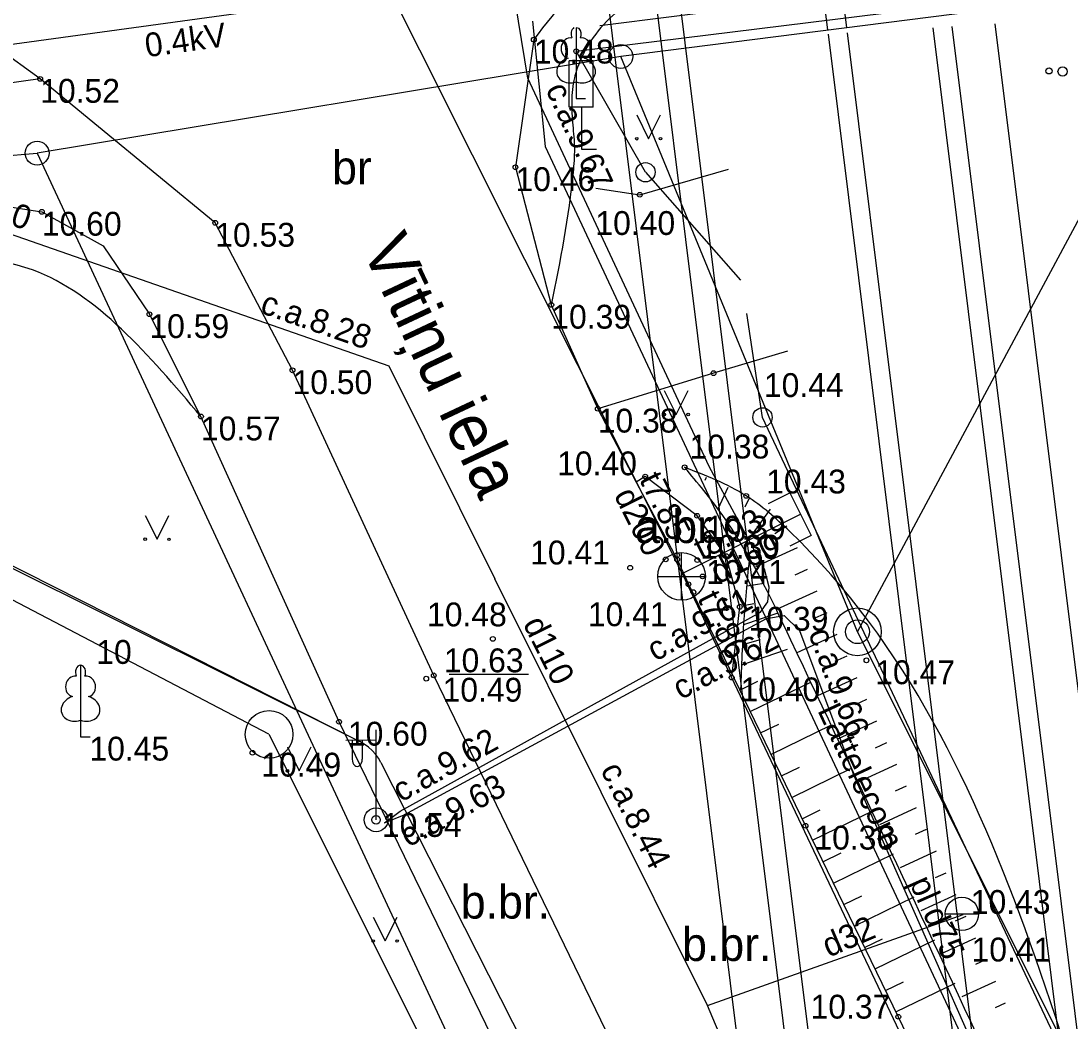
# Model space of a CAD drawing. Extents: x 502312.8 to 502402.4, y 308528.5 to 308602.
# Drawn here: x 502364.65 to 502386.67, y 308567.38 to 308588.36 of the extents above; entities that cross this region are included whole.
import ezdxf

# ---------------------------------------------------------------- set-up
doc = ezdxf.new("R2010")
doc.units = 0
for name, color, linetype in [('10', 7, 'Continuous'), ('24', 7, 'Continuous'), ('APGR_ELEM_####_####_#', 7, 'Continuous'), ('APGR_SARK_####_####_#', 7, 'Continuous'), ('APGS_ACRL_####_####_#', 7, 'Continuous'), ('APGS_ACRL_####_TKST_#', 7, 'Continuous'), ('APGS_ELEM_####_####_#', 7, 'Continuous'), ('APGS_VADP_ZSPR_####_I', 7, 'Continuous'), ('CELI_CAPM_####_####_#', 7, 'Continuous'), ('CELI_CMAL_####_####_#', 7, 'Continuous'), ('CELI_CSEG_####_TKST_#', 7, 'Continuous'), ('CELI_ELEM_####_####_#', 7, 'Continuous'), ('CELI_IELA_####_TKST_#', 7, 'Continuous'), ('ELEK_ACRL_####_####_#', 7, 'Continuous'), ('ELEK_VADP_ZSPR_####_#', 7, 'Continuous'), ('ELEK_VADV_ASP1_####_#', 7, 'Continuous'), ('ELEK_VADV_ZSPR_####_#', 7, 'Continuous'), ('ELEK_VADV_ZSPR_TKST_#', 7, 'Continuous'), ('Level 51-1', 7, 'Continuous'), ('NORB_ELEM_####_####_#', 7, 'Continuous'), ('NORB_ZOGS_BARJ_####_#', 7, 'Continuous'), ('NORB_ZOGS_ZSTP_####_#', 7, 'Continuous'), ('RELJ_AATZ_####_TKST_#', 7, 'Continuous'), ('RELJ_ELEM_####_####_#', 7, 'Continuous'), ('RELJ_NOGA_####_####_#', 7, 'Continuous'), ('RELJ_NOGL_####_####_#', 7, 'Continuous'), ('SAKK_KKAN_####_####_#', 7, 'Continuous'), ('SAKK_KKAN_####_TKST_#', 7, 'Continuous'), ('SKAN_ELEM_####_####_#', 7, 'Continuous'), ('SKAN_ELEM_PAST_TKST_#', 7, 'Continuous'), ('SKAN_VADP_PAST_####_I', 7, 'Continuous'), ('SKAN_VADP_PAST_TKST_I', 7, 'Continuous'), ('TERT_DIAM_####_TKST_#', 7, 'Continuous'), ('TERT_DZOG_####_####_#', 7, 'Continuous'), ('TERT_ELEM_####_####_#', 7, 'Continuous'), ('TERT_KONT_####_####_#', 7, 'Continuous'), ('UDTK_ELEM_####_####_#', 7, 'Continuous'), ('UDTK_ELEM_####_TKST_#', 7, 'Continuous'), ('UDTK_VADP_UDEN_####_#', 7, 'Continuous'), ('UDTK_VADP_UDEN_TKST_#', 7, 'Continuous')]:
    doc.layers.add(name, color=color, linetype=linetype)

msp = doc.modelspace()

# ---------------------------------------------------------------- linework, layer by layer
at = {"layer": '10'}
for centre in [(502377.227, 308587.621), (502364.984, 308585.593), (502382.191, 308575.562)]:
    msp.add_circle(centre, 0.25, dxfattribs=at)
at = {"layer": '24'}
for p, q in [((502402.407, 308590.821), (502377.227, 308587.621)), ((502377.227, 308587.621), (502364.984, 308585.593)), ((502382.191, 308575.562), (502377.227, 308587.621)), ((502343.246, 308583.821), (502364.984, 308585.593)), ((502364.984, 308585.593), (502381.693, 308549.732)), ((502394.734, 308550.484), (502382.191, 308575.562))]:
    msp.add_line(p, q, dxfattribs=at)
at = {"layer": 'APGR_ELEM_####_####_#'}
for centre in [(502382.19, 308575.56), (502369.85, 308573.41)]:
    msp.add_circle(centre, 0.5, dxfattribs=at)
at = {"layer": 'APGR_SARK_####_####_#'}
for p, q in [((502382.191, 308575.562), (502387.25, 308584.993)), ((502369.848, 308573.414), (502363.114, 308576.934)), ((502382.191, 308575.562), (502394.734, 308550.484)), ((502369.848, 308573.413), (502381.693, 308549.732))]:
    msp.add_line(p, q, dxfattribs=at)
at = {"layer": 'APGS_ACRL_####_####_#'}
for points in [[(502372.273, 308571.554), (502372.6, 308571.798), (502380.155, 308575.975), (502380.312, 308576.186), (502380.335, 308576.496), (502380.24, 308576.87), (502379.077, 308579.027), (502375.276, 308587.169), (502373.291, 308599.286)], [(502372.273, 308571.554), (502372.68, 308571.725), (502380.284, 308575.836), (502380.655, 308575.903), (502380.972, 308575.586), (502382.116, 308572.55), (502384.894, 308566.257), (502388.272, 308559.63), (502390.397, 308554.024), (502392.869, 308547.38), (502392.92, 308547.155)]]:
    msp.add_lwpolyline(points, dxfattribs=at)
at = {"layer": 'APGS_ELEM_####_####_#'}
for p, q in [((502372.093, 308571.62), (502372.093, 308573.502)), ((502372.093, 308573.286), (502371.458, 308573.281)), ((502371.593, 308573.282), (502371.593, 308572.89)), ((502371.803, 308573.284), (502371.803, 308572.89))]:
    msp.add_line(p, q, dxfattribs=at)
for radius in [0.25, 0.09]:
    msp.add_circle((502372.093, 308571.62), radius, dxfattribs=at)
msp.add_ellipse((502371.698, 308572.89), major_axis=(0, 0.151), ratio=0.695971, start_param=1.570796, end_param=4.712389, dxfattribs=at)
at = {"layer": 'APGS_VADP_ZSPR_####_I'}
msp.add_lwpolyline([(502372.273, 308571.554), (502372.68, 308571.725), (502380.284, 308575.836), (502380.655, 308575.903), (502380.972, 308575.586), (502382.116, 308572.55), (502384.894, 308566.257), (502388.272, 308559.63), (502390.397, 308554.024), (502392.869, 308547.38), (502392.92, 308547.155)], dxfattribs=at)
at = {"layer": 'CELI_CAPM_####_####_#'}
for points in [[(502373.303, 308574.647), (502370.341, 308581.042), (502368.721, 308584.133), (502365.049, 308587.15), (502364.156, 308587.797), (502361.753, 308588.821), (502359.465, 308589.651)], [(502375.403, 308587.973), (502375.017, 308585.298), (502375.769, 308582.415), (502376.743, 308580.237), (502377.549, 308578.698)], [(502378.409, 308577.074), (502378.645, 308576.556), (502381.101, 308571.495), (502383.047, 308567.49), (502386.95, 308559.382), (502387.372, 308558.481), (502387.692, 308557.774), (502387.933, 308557.255), (502388.418, 308556.115), (502389.212, 308554.306), (502389.599, 308553.373), (502390.383, 308551.504), (502391.144, 308549.652), (502391.872, 308547.788), (502392.589, 308545.929), (502393.393, 308543.693), (502393.705, 308542.827)], [(502392.53, 308528.536), (502392.273, 308529.412), (502391.34, 308532.322), (502390.324, 308535.341), (502389.269, 308538.416), (502388.272, 308541.254), (502387.358, 308543.683), (502386.314, 308546.51), (502385.198, 308549.256), (502384.849, 308550.113), (502383.229, 308553.89), (502382.013, 308556.65), (502380.717, 308559.374), (502377.909, 308565.152), (502373.303, 308574.647)]]:
    msp.add_lwpolyline(points, dxfattribs=at)
msp.add_arc((502385.433, 308580.61), 12.443, 121.1953, 143.7174, dxfattribs=at)
at = {"layer": 'CELI_CMAL_####_####_#'}
msp.add_line((502366.368, 308583.65), (502367.34, 308582.218), dxfattribs=at)
for points in [[(502365.049, 308587.15), (502341.875, 308583.905), (502332.578, 308582.643)], [(502376.706, 308584.859), (502377.624, 308584.722), (502379.489, 308585.258)], [(502362.932, 308584.696), (502365.084, 308584.364), (502366.368, 308583.65)], [(502371.317, 308573.674), (502368.421, 308580.073), (502367.34, 308582.218)], [(502380.722, 308581.444), (502379.172, 308580.982), (502376.743, 308580.237)], [(502379.559, 308574.672), (502379.722, 308576.084), (502379.44, 308577.147), (502378.827, 308577.993), (502377.74, 308578.814), (502377.549, 308578.698), (502378.409, 308577.074)], [(502390.232, 308528.536), (502388.865, 308532.737), (502388.043, 308535.197), (502387.28, 308537.476), (502386.263, 308540.301), (502385.235, 308543.076), (502384.524, 308544.988), (502383.511, 308547.559), (502382.468, 308550.05), (502379.873, 308556.046), (502379.438, 308556.939), (502376.448, 308563.104), (502371.317, 308573.674)]]:
    msp.add_lwpolyline(points, dxfattribs=at)
at = {"layer": 'CELI_ELEM_####_####_#'}
for p, q in [((502376.647, 308587.526), (502376.147, 308587.526)), ((502376.147, 308586.557), (502376.147, 308587.526)), ((502376.647, 308586.557), (502376.647, 308587.526)), ((502376.647, 308586.557), (502376.147, 308586.557)), ((502376.401, 308586.557), (502376.401, 308585.679)), ((502376.401, 308585.679), (502376.716, 308585.679))]:
    msp.add_line(p, q, dxfattribs=at)
at = {"layer": 'ELEK_ACRL_####_####_#'}
msp.add_line((502361.181, 308578.53), (502371.756, 308573.259), dxfattribs=at)
at = {"layer": 'ELEK_VADP_ZSPR_####_#'}
for p, q in [((502364.105, 308577.13), (502371.756, 308573.259)), ((502372.196, 308572.819), (502383.39, 308550.751))]:
    msp.add_line(p, q, dxfattribs=at)
msp.add_lwpolyline([(502372.196, 308572.819), (502372.144, 308572.91), (502372.082, 308572.995), (502372.011, 308573.074), (502371.932, 308573.145), (502371.847, 308573.207), (502371.756, 308573.259)], dxfattribs=at)
at = {"layer": 'ELEK_VADV_ASP1_####_#'}
msp.add_line((502392.53, 308528.536), (502385.08, 308588.302), dxfattribs=at)
for points in [[(502377.051, 308588.051), (502375.312, 308602.001)], [(502378.08, 308587.88), (502376.319, 308602.001)], [(502378.58, 308587.91), (502376.823, 308602.001)], [(502381.57, 308588.173), (502379.846, 308602.001)], [(502381.966, 308588.223), (502380.249, 308602.001)], [(502389.406, 308528.536), (502381.98, 308588.115)], [(502391.22, 308528.536), (502383.78, 308588.224)], [(502391.623, 308528.536), (502384.18, 308588.248)], [(502384.469, 308528.536), (502377.051, 308588.051)], [(502385.476, 308528.536), (502378.08, 308587.88)], [(502385.98, 308528.536), (502378.58, 308587.91)], [(502389.003, 308528.536), (502381.58, 308588.091)]]:
    msp.add_lwpolyline(points, dxfattribs=at)
at = {"layer": 'ELEK_VADV_ZSPR_####_#'}
msp.add_line((502352.427, 308586.209), (502386.227, 308590.894), dxfattribs=at)
at = {"layer": 'Level 51-1'}
for p, q in [((502343.246, 308583.821), (502364.984, 308585.593)), ((502364.984, 308585.593), (502381.693, 308549.732))]:
    msp.add_line(p, q, dxfattribs=at)
at = {"layer": 'NORB_ELEM_####_####_#'}
for centre in [(502377.744, 308585.194), (502380.198, 308580.055)]:
    msp.add_circle(centre, 0.202, dxfattribs=at)
at = {"layer": 'NORB_ZOGS_BARJ_####_#'}
for p, q in [((502377.744, 308585.194), (502379.735, 308582.934)), ((502380.198, 308580.055), (502379.872, 308582.231))]:
    msp.add_line(p, q, dxfattribs=at)
at = {"layer": 'NORB_ZOGS_ZSTP_####_#'}
msp.add_line((502388.785, 308561.881), (502380.198, 308580.055), dxfattribs=at)
for points in [[(502377.471, 308587.877), (502386.427, 308588.988)], [(502377.744, 308585.194), (502376.292, 308587.731), (502377.471, 308587.877)]]:
    msp.add_lwpolyline(points, dxfattribs=at)
at = {"layer": 'RELJ_AATZ_####_TKST_#'}
msp.add_line((502373.624, 308574.671), (502375.291, 308574.671), dxfattribs=at)
at = {"layer": 'RELJ_ELEM_####_####_#'}
for centre in [(502375.403, 308587.973), (502376.292, 308587.731), (502365.049, 308587.15), (502375.017, 308585.298), (502377.624, 308584.722), (502365.084, 308584.364), (502368.721, 308584.133), (502375.769, 308582.415), (502367.34, 308582.218), (502370.341, 308581.042), (502379.172, 308580.982), (502376.743, 308580.237), (502368.421, 308580.073), (502377.74, 308578.814), (502378.565, 308579.008), (502379.858, 308578.409), (502378.827, 308577.993), (502378.992, 308577.546), (502378.168, 308577.079), (502378.407, 308577.167), (502378.409, 308577.074), (502378.832, 308577.063), (502379.44, 308577.147), (502377.423, 308576.902), (502378.941, 308576.721), (502378.645, 308576.556), (502378.749, 308576.393), (502379.722, 308576.084), (502374.543, 308575.412), (502382.378, 308574.962), (502373.303, 308574.647), (502373.146, 308574.578), (502379.551, 308574.603), (502371.317, 308573.674), (502369.502, 308573.025), (502381.101, 308571.495), (502383.047, 308567.49)]:
    msp.add_circle(centre, 0.05, dxfattribs=at)
at = {"layer": 'RELJ_NOGA_####_####_#'}
for p, q in [((502378.565, 308579.008), (502378.565, 308579.007)), ((502379.019, 308578.798), (502378.987, 308578.729)), ((502379.472, 308578.588), (502379.261, 308578.131)), ((502379.926, 308578.377), (502379.825, 308578.172)), ((502380.359, 308578.128), (502379.804, 308577.361)), ((502380.707, 308577.774), (502380.457, 308577.615)), ((502380.924, 308577.324), (502380.052, 308576.923)), ((502381.133, 308576.869), (502380.876, 308576.751)), ((502379.874, 308576.521), (502380.226, 308576.583)), ((502381.341, 308576.415), (502380.493, 308576.025)), ((502379.838, 308576.121), (502380.017, 308576.155)), ((502379.808, 308575.713), (502380.524, 308575.961)), ((502381.55, 308575.96), (502381.296, 308575.844)), ((502379.786, 308575.295), (502380.154, 308575.397)), ((502381.758, 308575.506), (502380.92, 308575.122)), ((502379.768, 308574.866), (502380.724, 308575.196)), ((502381.967, 308575.051), (502381.718, 308574.937)), ((502379.721, 308574.339), (502380.104, 308574.525)), ((502379.939, 308573.89), (502381.214, 308574.508)), ((502382.175, 308574.597), (502381.353, 308574.22)), ((502382.383, 308574.142), (502382.139, 308574.031)), ((502380.157, 308573.44), (502380.539, 308573.625)), ((502380.376, 308572.99), (502381.647, 308573.607)), ((502382.591, 308573.688), (502381.786, 308573.319)), ((502382.799, 308573.233), (502382.56, 308573.124)), ((502380.594, 308572.54), (502380.975, 308572.725)), ((502380.812, 308572.09), (502382.081, 308572.706)), ((502383.007, 308572.778), (502382.22, 308572.418)), ((502383.215, 308572.324), (502382.982, 308572.217)), ((502381.03, 308571.641), (502381.411, 308571.825)), ((502381.249, 308571.191), (502382.514, 308571.806)), ((502383.423, 308571.869), (502382.653, 308571.517)), ((502383.631, 308571.414), (502383.402, 308571.31)), ((502381.467, 308570.741), (502381.846, 308570.925)), ((502383.838, 308570.959), (502383.086, 308570.616)), ((502381.686, 308570.291), (502382.948, 308570.904)), ((502384.046, 308570.504), (502383.823, 308570.403)), ((502384.254, 308570.05), (502383.519, 308569.714)), ((502381.904, 308569.842), (502382.282, 308570.025)), ((502382.123, 308569.392), (502383.38, 308570.003)), ((502384.461, 308569.595), (502384.243, 308569.495)), ((502382.341, 308568.942), (502382.718, 308569.125)), ((502382.56, 308568.492), (502383.812, 308569.101)), ((502384.669, 308569.14), (502383.949, 308568.812)), ((502384.876, 308568.685), (502384.663, 308568.587)), ((502382.778, 308568.043), (502383.153, 308568.225)), ((502382.997, 308567.593), (502384.241, 308568.197)), ((502385.084, 308568.23), (502384.378, 308567.908)), ((502385.291, 308567.775), (502385.081, 308567.679))]:
    msp.add_line(p, q, dxfattribs=at)
for points in [[(502392.938, 308547.462), (502392.327, 308552.238), (502392.05, 308552.998), (502389.203, 308559.21), (502380.766, 308577.667), (502379.858, 308578.409), (502378.565, 308579.008)], [(502379.747, 308574.352), (502379.815, 308575.818), (502379.932, 308577.142)]]:
    msp.add_spline(points, degree=3, dxfattribs=at)
at = {"layer": 'RELJ_NOGL_####_####_#'}
msp.add_spline([(502392.938, 308547.462), (502388.885, 308557.685), (502380.794, 308575.385), (502379.35, 308578.02), (502378.565, 308579.008)], degree=3, dxfattribs=at)
at = {"layer": 'SAKK_KKAN_####_####_#'}
msp.add_line((502375.641, 308585.734), (502378.865, 308578.852), dxfattribs=at)
for points in [[(502375.372, 308588.364), (502375.641, 308585.734)], [(502378.865, 308578.852), (502390.92, 308553.118), (502393.046, 308548.902)]]:
    msp.add_lwpolyline(points, dxfattribs=at)
at = {"layer": 'SKAN_ELEM_####_####_#'}
for p, q in [((502378.501, 308576.222), (502378.501, 308577.222)), ((502378.001, 308576.722), (502379.001, 308576.722))]:
    msp.add_line(p, q, dxfattribs=at)
msp.add_lwpolyline([(502380.324, 308578.249), (502380.771, 308578.473), (502381.219, 308577.579), (502380.772, 308577.355)], dxfattribs=at)
msp.add_circle((502378.501, 308576.722), 0.5, dxfattribs=at)
at = {"layer": 'SKAN_VADP_PAST_####_I'}
for points in [[(502369.581, 308594.569), (502373.002, 308587.759)], [(502373.002, 308587.759), (502378.517, 308576.782), (502387.809, 308557.18), (502392.481, 308545.051), (502396.902, 308528.536)], [(502378.517, 308576.782), (502380.995, 308578.026)]]:
    msp.add_lwpolyline(points, dxfattribs=at)
at = {"layer": 'TERT_DZOG_####_####_#'}
msp.add_line((502376.789, 308588.271), (502386.386, 308589.481), dxfattribs=at)
at = {"layer": 'TERT_ELEM_####_####_#'}
for p, q in [((502376.353, 308588.209), (502376.289, 308588.219)), ((502376.289, 308588.219), (502376.289, 308587.087)), ((502376.379, 308588.008), (502376.378, 308588.009)), ((502376.289, 308587.087), (502376.289, 308586.74)), ((502376.289, 308586.74), (502376.489, 308586.74)), ((502377.56, 308586.397), (502377.81, 308585.897)), ((502377.81, 308585.897), (502378.06, 308586.397)), ((502378.139, 308580.616), (502378.389, 308580.116)), ((502378.389, 308580.116), (502378.639, 308580.616)), ((502367.25, 308578), (502367.5, 308577.5)), ((502367.5, 308577.5), (502367.75, 308578)), ((502365.896, 308573.708), (502365.896, 308573.361)), ((502365.896, 308573.361), (502366.096, 308573.361)), ((502370.233, 308573.148), (502370.483, 308572.648)), ((502370.483, 308572.648), (502370.733, 308573.148)), ((502372.036, 308569.579), (502372.286, 308569.079)), ((502372.286, 308569.079), (502372.536, 308569.579))]:
    msp.add_line(p, q, dxfattribs=at)
for points in [[(502365.896, 308574.861), (502365.896, 308573.708)], [(502365.986, 308574.629), (502365.985, 308574.63)]]:
    msp.add_lwpolyline(points, dxfattribs=at)
for centre, radius in [((502386.208, 308587.318), 0.064), ((502386.492, 308587.305), 0.096), ((502377.56, 308585.897), 0.028), ((502378.06, 308585.897), 0.0263), ((502378.138, 308580.115), 0.028), ((502378.638, 308580.115), 0.0263), ((502367.25, 308577.5), 0.028), ((502367.75, 308577.5), 0.0263), ((502370.233, 308572.647), 0.028), ((502370.733, 308572.647), 0.0263), ((502372.035, 308569.078), 0.028), ((502372.535, 308569.078), 0.0263)]:
    msp.add_circle(centre, radius, dxfattribs=at)
for centre, major_axis, ratio, start_param, end_param in [((502376.289, 308588.09), (0, -0.15), 0.707107, 3.576228, 5.287485), ((502376.289, 308588.09), (0, -0.15), 0.707107, 0.995701, 2.486101), ((502376.161, 308587.795), (-0.039, -0.212), 0.861323, 3.141593, 6.283185), ((502376.417, 308587.795), (0.039, -0.212), 0.861323, 0, 3.141593), ((502376.199, 308587.333), (0.307, 0.095), 0.814445, 1.570796, 4.752015), ((502376.379, 308587.333), (-0.307, 0.095), 0.814445, 1.531171, 4.712389), ((502365.896, 308574.711), (0, -0.15), 0.707107, 3.14537, 5.287485), ((502365.896, 308574.711), (0, -0.15), 0.707107, 0.995701, 3.137816), ((502365.768, 308574.416), (-0.039, -0.212), 0.861323, 3.141593, 6.283185), ((502366.024, 308574.416), (0.039, -0.212), 0.861323, 0, 3.141593), ((502365.806, 308573.954), (0.307, 0.095), 0.814445, 1.570796, 4.752015), ((502365.986, 308573.954), (-0.307, 0.095), 0.814445, 1.531171, 4.712389)]:
    msp.add_ellipse(centre, major_axis=major_axis, ratio=ratio, start_param=start_param, end_param=end_param, dxfattribs=at)
at = {"layer": 'TERT_KONT_####_####_#'}
for points in [[(502402.407, 308591.849), (502400.199, 308591.585), (502397.99, 308591.343), (502395.524, 308591.079), (502393.061, 308590.798), (502388.136, 308590.207), (502383.214, 308589.602), (502378.291, 308589.019), (502378.089, 308589.019), (502377.771, 308588.924), (502377.468, 308588.778), (502376.927, 308588.354), (502376.51, 308587.802), (502376.359, 308587.494), (502376.255, 308587.175), (502376.197, 308586.68), (502376.22, 308586.182), (502376.253, 308585.686), (502376.226, 308585.194), (502375.769, 308582.415)], [(502368.421, 308580.073), (502364.888, 308583.145), (502359.074, 308582.726), (502336.999, 308579.84), (502335.385, 308579.318), (502336.097, 308569.387), (502336.741, 308557.487), (502335.314, 308546.766)]]:
    msp.add_spline(points, degree=3, dxfattribs=at)
at = {"layer": 'UDTK_ELEM_####_####_#'}
msp.add_line((502384.03, 308569.647), (502384.732, 308569.647), dxfattribs=at)
msp.add_circle((502384.381, 308569.647), 0.351, dxfattribs=at)
at = {"layer": 'UDTK_VADP_UDEN_####_#'}
for p, q in [((502379.047, 308567.724), (502374.586, 308576.669)), ((502379.047, 308567.724), (502384.406, 308569.635)), ((502387.742, 308547.347), (502379.047, 308567.724))]:
    msp.add_line(p, q, dxfattribs=at)
msp.add_lwpolyline([(502350.697, 308580.556), (502351.744, 308583.627), (502361.023, 308585.084), (502372.36, 308581.134), (502374.586, 308576.669)], dxfattribs=at)

# ---------------------------------------------------------------- texts
at = {"layer": 'APGS_ACRL_####_TKST_#'}
for s, rotation, p in [('c.a.9.67', 294.6236, (502375.641, 308586.935)), ('c.a.9.61', 28.9373, (502377.952, 308574.928)), ('c.a.9.62', 28.3973, (502378.486, 308574.125)), ('c.a.9.66', 290.647, (502381.153, 308575.532)), ('c.a.9.62', 28.9373, (502372.616, 308571.978)), ('c.a.9.63', 28.3973, (502372.768, 308571.034)), ('pl d75', 293.8187, (502383.269, 308570.309))]:
    msp.add_text(s, height=0.5, rotation=rotation, dxfattribs=at).set_placement(p)
at = {"layer": 'CELI_CSEG_####_TKST_#'}
for s, p in [('br', (502371.172, 308584.943)), ('a.br.', (502377.526, 308577.421)), ('b.br.', (502373.871, 308569.549)), ('b.br.', (502378.513, 308568.661))]:
    msp.add_text(s, height=0.7, dxfattribs=at).set_placement(p)
at = {"layer": 'CELI_IELA_####_TKST_#'}
msp.add_text('Vītiņu iela', height=1, rotation=295.1517, dxfattribs=at).set_placement((502371.783, 308583.601))
at = {"layer": 'ELEK_VADV_ZSPR_TKST_#'}
msp.add_text('0.4kV', height=0.5, rotation=7.8913, dxfattribs=at).set_placement((502367.282, 308587.603))
at = {"layer": 'RELJ_AATZ_####_TKST_#'}
for s, p in [('10.48', (502375.403, 308587.473)), ('10.52', (502365.049, 308586.65)), ('10.46', (502375.017, 308584.798)), ('10.60', (502365.084, 308583.864)), (' 10.40', (502376.508, 308583.879)), ('10.53', (502368.721, 308583.633)), ('10.39', (502375.769, 308581.915)), ('10.59', (502367.34, 308581.718)), ('10.50', (502370.341, 308580.542)), (' 10.44', (502380.043, 308580.482)), ('10.38', (502376.743, 308579.737)), ('10.57', (502368.421, 308579.573)), (' 10.38', (502378.483, 308579.193)), (' 10.40', (502375.705, 308578.841)), (' 10.43', (502380.089, 308578.46)), (' 10.39', (502378.827, 308577.493)), (' 10.41', (502375.139, 308576.972)), (' 10.41', (502378.832, 308576.563)), (' 10.48', (502372.977, 308575.674)), (' 10.39', (502379.722, 308575.584)), (' 10.63', (502373.329, 308574.712)), (' 10.47', (502382.378, 308574.462)), (' 10.49', (502373.303, 308574.096)), (' 10.40', (502379.551, 308574.103)), (' 10.60', (502371.317, 308573.174)), (' 10.45', (502365.896, 308572.861)), (' 10.49', (502369.502, 308572.525)), (' 10.54', (502372.031, 308571.261)), (' 10.36', (502381.101, 308570.995)), (' 10.37', (502381.022, 308567.452))]:
    msp.add_text(s, height=0.5, dxfattribs=at).set_placement(p)
at = {"layer": 'SAKK_KKAN_####_TKST_#'}
msp.add_text('Lattelecom', height=0.5, rotation=295.1018, dxfattribs=at).set_placement((502381.344, 308573.914))
at = {"layer": 'SKAN_ELEM_PAST_TKST_#'}
for s, p in [('10.39', (502378.892, 308577.093)), (' 10.41', (502376.35, 308575.678))]:
    msp.add_text(s, height=0.5, dxfattribs=at).set_placement(p)
at = {"layer": 'SKAN_VADP_PAST_TKST_I'}
for s, rotation, p in [('t7.85', 296.6745, (502377.605, 308578.755)), ('d200', 296.6745, (502377.075, 308578.426)), ('t8.93', 26.6575, (502378.922, 308577.054)), ('d160', 26.6575, (502379.267, 308576.553)), ('t7.86', 296.6745, (502378.824, 308576.265))]:
    msp.add_text(s, height=0.5, rotation=rotation, dxfattribs=at).set_placement(p)
at = {"layer": 'TERT_DIAM_####_TKST_#'}
msp.add_text('10', height=0.5, dxfattribs=at).set_placement((502366.226, 308574.888))
at = {"layer": 'UDTK_ELEM_####_TKST_#'}
for s, p in [(' 10.43', (502384.381, 308569.647)), (' 10.41', (502384.397, 308568.649))]:
    msp.add_text(s, height=0.5, dxfattribs=at).set_placement(p)
at = {"layer": 'UDTK_VADP_UDEN_TKST_#'}
for s, rotation, p in [('d110', 340.7908, (502363.348, 308584.461)), ('c.a.8.28', 340.7908, (502369.637, 308582.254)), ('d110', 296.5035, (502375.166, 308575.73)), ('c.a.8.44', 296.5035, (502376.791, 308572.668)), ('d32', 23.1087, (502381.586, 308568.728))]:
    msp.add_text(s, height=0.5, rotation=rotation, dxfattribs=at).set_placement(p)

doc.saveas('drawing.dxf')
